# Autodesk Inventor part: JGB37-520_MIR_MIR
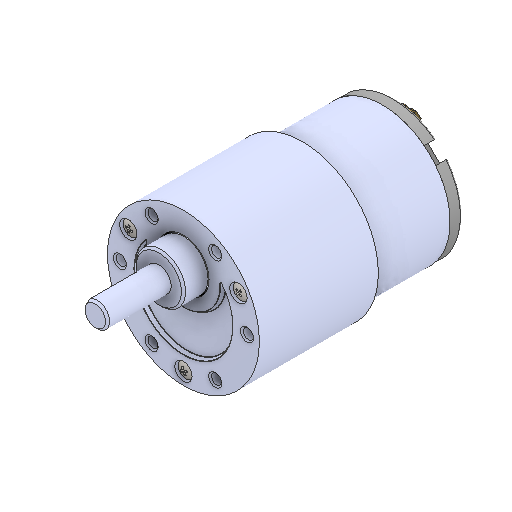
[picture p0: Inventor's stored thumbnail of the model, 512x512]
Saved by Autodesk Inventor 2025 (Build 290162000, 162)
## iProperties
Created: 2017-03
Part Number: JGB37-520_MIR_MIR
Material: Generico
Description: STEP AP214
Document SubType Name: Modeling
Designer: R5800u
Density: 1 g/cm^3
Appearance: Default
Title: JGB37-520.STEP
Sending System: SolidWorks 2017
Preprocessor: SwSTEP 2.0
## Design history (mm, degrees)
derived "JGB37-520_MIR.ipt"
feature "Solido1::JGB37-520_MIR.ipt"
feature "Solido2::JGB37-520_MIR.ipt"
feature "Solido3::JGB37-520_MIR.ipt"
feature "Solido4::JGB37-520_MIR.ipt"
feature "Solido5::JGB37-520_MIR.ipt"
feature "Solido6::JGB37-520_MIR.ipt"
feature "Solido7::JGB37-520_MIR.ipt"
feature "Solido8::JGB37-520_MIR.ipt"
feature "Solido9::JGB37-520_MIR.ipt"
feature "Solido10::JGB37-520_MIR.ipt"
feature "Solido11::JGB37-520_MIR.ipt"
tag "Lavorazione contrassegno1"
node "Solido1"
node "Solido2"
node "Solido3"
node "Solido4"
node "Solido5"
node "Solido6"
node "Solido7"
node "Solido8"
node "Solido9"
node "Solido10"
node "Solido11"
